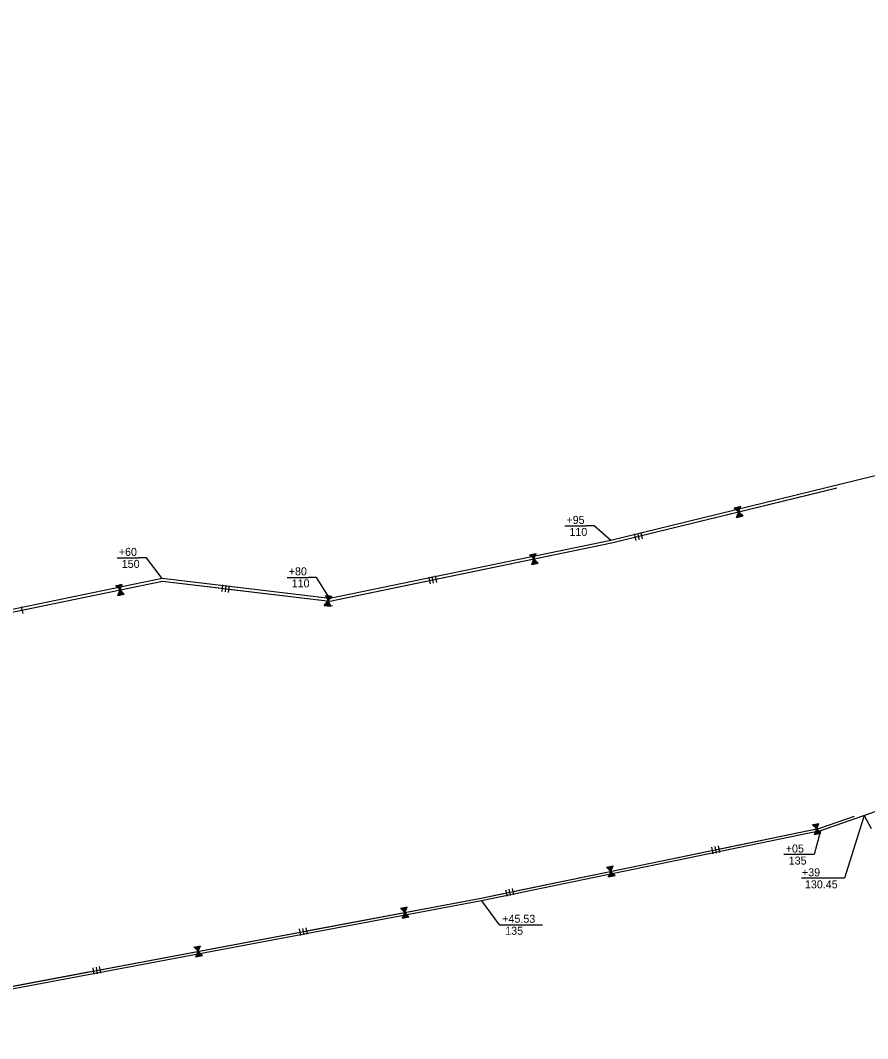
# Model space of a CAD drawing. Extents: x 979729 to 993523, y 1834148 to 1845433.
# Drawn here: x 989431 to 990066, y 1838597 to 1839360 of the extents above; entities that cross this region are included whole.
import ezdxf

# ---------------------------------------------------------------- set-up
doc = ezdxf.new("R2010")
doc.units = 0
for name, color, linetype in [('42', 7, 'Continuous'), ('51', 7, 'Continuous'), ('53', 7, 'Continuous'), ('R_Draft', 7, 'Continuous')]:
    doc.layers.add(name, color=color, linetype=linetype)

msp = doc.modelspace()

# ---------------------------------------------------------------- linework, layer by layer
at = {"layer": '42'}
for p, q in [((989873.61, 1838968.68), (990042.64, 1839010)), ((989967.98, 1838993.05), (989969, 1838995.86)), ((989968.16, 1838992.82), (989969.29, 1838995.93)), ((989968.36, 1838992.65), (989969.58, 1838996)), ((989968.56, 1838992.45), (989969.87, 1838996.07)), ((989968.77, 1838992.31), (989970.16, 1838996.15)), ((989968.96, 1838992.09), (989970.46, 1838996.22)), ((989969.02, 1838992), (989970.55, 1838996.24)), ((989965.7, 1838995.05), (989969.02, 1838992)), ((989965.76, 1838995.01), (989965.79, 1838995.08)), ((989965.97, 1838994.85), (989966.08, 1838995.15)), ((989966.16, 1838994.65), (989966.37, 1838995.22)), ((989966.37, 1838994.48), (989966.66, 1838995.29)), ((989966.56, 1838994.28), (989966.95, 1838995.36)), ((989966.76, 1838994.08), (989967.25, 1838995.43)), ((989966.96, 1838993.92), (989967.54, 1838995.5)), ((989967.19, 1838993.81), (989967.77, 1838995.42)), ((989967.37, 1838993.58), (989968.12, 1838995.65)), ((989967.48, 1838987.77), (989969.02, 1838992)), ((989967.58, 1838993.41), (989968.41, 1838995.72)), ((989967.7, 1838988.34), (989968.15, 1838987.93)), ((989967.76, 1838993.18), (989968.71, 1838995.79)), ((989967.81, 1838988.58), (989968.44, 1838988)), ((989967.89, 1838988.85), (989968.74, 1838988.08)), ((989967.97, 1838989.12), (989969.03, 1838988.15)), ((989968.07, 1838989.36), (989969.32, 1838988.22)), ((989968.23, 1838989.56), (989969.49, 1838988.4)), ((989968.28, 1838989.85), (989969.9, 1838988.36)), ((989968.39, 1838990.09), (989970.2, 1838988.43)), ((989968.44, 1838990.38), (989970.49, 1838988.5)), ((989968.57, 1838990.6), (989970.78, 1838988.57)), ((989968.63, 1838990.89), (989971.07, 1838988.65)), ((989968.74, 1838991.13), (989971.36, 1838988.72)), ((989968.81, 1838991.4), (989971.65, 1838988.79)), ((989968.94, 1838991.62), (989971.95, 1838988.86)), ((989969, 1838991.91), (989972.24, 1838988.93)), ((989969.02, 1838992), (989972.33, 1838988.95)), ((989967.52, 1838987.83), (989967.57, 1838987.79)), ((989967.63, 1838988.08), (989967.86, 1838987.86)), ((989890.71, 1838975.44), (989891.9, 1838970.58)), ((989893.14, 1838976.03), (989894.33, 1838971.17)), ((989895.57, 1838976.62), (989896.75, 1838971.77)), ((989662.7, 1838925.14), (989873.61, 1838968.68)), ((989812.34, 1838959.86), (989815.55, 1838956.7)), ((989812.41, 1838959.82), (989812.43, 1838959.88)), ((989812.61, 1838959.65), (989812.73, 1838959.94)), ((989812.79, 1838959.44), (989813.02, 1838960.01)), ((989813, 1838959.27), (989813.32, 1838960.07)), ((989813.18, 1838959.06), (989813.61, 1838960.13)), ((989813.37, 1838958.85), (989813.9, 1838960.19)), ((989813.57, 1838958.68), (989814.2, 1838960.25)), ((989813.79, 1838958.57), (989814.43, 1838960.15)), ((989813.96, 1838958.33), (989814.79, 1838960.37)), ((989814.16, 1838958.16), (989815.08, 1838960.43)), ((989814.34, 1838957.92), (989815.38, 1838960.49)), ((989814.55, 1838957.78), (989815.67, 1838960.55)), ((989814.72, 1838957.54), (989815.96, 1838960.61)), ((989814.92, 1838957.37), (989816.26, 1838960.67)), ((989815.11, 1838957.16), (989816.55, 1838960.73)), ((989815.32, 1838957.02), (989816.85, 1838960.79)), ((989815.49, 1838956.78), (989817.14, 1838960.86)), ((989815.55, 1838956.7), (989817.24, 1838960.88)), ((989813.86, 1838952.52), (989815.55, 1838956.7)), ((989813.9, 1838952.59), (989813.95, 1838952.54)), ((989814.02, 1838952.82), (989814.24, 1838952.6)), ((989814.11, 1838953.09), (989814.54, 1838952.66)), ((989814.22, 1838953.32), (989814.83, 1838952.72)), ((989814.31, 1838953.59), (989815.13, 1838952.78)), ((989814.4, 1838953.85), (989815.42, 1838952.84)), ((989814.51, 1838954.09), (989815.71, 1838952.9)), ((989814.67, 1838954.28), (989815.89, 1838953.08)), ((989814.74, 1838954.57), (989816.3, 1838953.02)), ((989814.85, 1838954.81), (989816.6, 1838953.09)), ((989814.92, 1838955.09), (989816.89, 1838953.15)), ((989815.06, 1838955.31), (989817.19, 1838953.21)), ((989815.12, 1838955.6), (989817.48, 1838953.27)), ((989815.24, 1838955.83), (989817.77, 1838953.33)), ((989815.33, 1838956.1), (989818.07, 1838953.39)), ((989815.46, 1838956.31), (989818.36, 1838953.45)), ((989815.53, 1838956.6), (989818.66, 1838953.51)), ((989815.55, 1838956.7), (989818.75, 1838953.53)), ((989736.69, 1838942.97), (989737.71, 1838938.07)), ((989739.14, 1838943.48), (989740.15, 1838938.58)), ((989741.59, 1838943.98), (989742.6, 1838939.09)), ((989341.75, 1838899.73), (989537.09, 1838940.06)), ((989502.12, 1838936.66), (989505.32, 1838933.5)), ((989502.18, 1838936.62), (989502.21, 1838936.68)), ((989502.38, 1838936.45), (989502.5, 1838936.74)), ((989502.57, 1838936.24), (989502.8, 1838936.81)), ((989502.77, 1838936.07), (989503.09, 1838936.87)), ((989502.95, 1838935.86), (989503.39, 1838936.93)), ((989503.14, 1838935.65), (989503.68, 1838936.99)), ((989503.34, 1838935.48), (989503.97, 1838937.05)), ((989503.56, 1838935.37), (989504.21, 1838936.96)), ((989503.74, 1838935.13), (989504.56, 1838937.17)), ((989503.94, 1838934.96), (989504.86, 1838937.23)), ((989504.11, 1838934.72), (989505.15, 1838937.29)), ((989504.32, 1838934.58), (989505.45, 1838937.35)), ((989504.5, 1838934.34), (989505.74, 1838937.41)), ((989504.7, 1838934.17), (989506.03, 1838937.47)), ((989504.88, 1838933.96), (989506.33, 1838937.53)), ((989505.09, 1838933.82), (989506.62, 1838937.59)), ((989505.27, 1838933.58), (989506.92, 1838937.66)), ((989505.32, 1838933.5), (989507.01, 1838937.68)), ((989537.09, 1838940.06), (989662.7, 1838925.14)), ((989582.13, 1838937.23), (989581.54, 1838932.26)), ((989584.62, 1838936.93), (989584.03, 1838931.97)), ((989587.1, 1838936.64), (989586.51, 1838931.67)), ((989503.63, 1838929.32), (989505.32, 1838933.5)), ((989503.68, 1838929.39), (989503.72, 1838929.34)), ((989503.79, 1838929.62), (989504.02, 1838929.4)), ((989503.88, 1838929.89), (989504.31, 1838929.46)), ((989504, 1838930.12), (989504.61, 1838929.52)), ((989504.08, 1838930.39), (989504.9, 1838929.58)), ((989504.17, 1838930.65), (989505.2, 1838929.64)), ((989504.29, 1838930.89), (989505.49, 1838929.7)), ((989504.45, 1838931.08), (989505.67, 1838929.88)), ((989504.51, 1838931.37), (989506.08, 1838929.82)), ((989504.63, 1838931.61), (989506.37, 1838929.89)), ((989504.69, 1838931.89), (989506.67, 1838929.95)), ((989504.83, 1838932.11), (989506.96, 1838930.01)), ((989504.9, 1838932.4), (989507.26, 1838930.07)), ((989505.01, 1838932.63), (989507.55, 1838930.13)), ((989505.1, 1838932.9), (989507.84, 1838930.19)), ((989505.24, 1838933.11), (989508.14, 1838930.25)), ((989505.3, 1838933.4), (989508.43, 1838930.31)), ((989505.32, 1838933.5), (989508.53, 1838930.33)), ((989659.24, 1838929.33), (989661.28, 1838925.31)), ((989659.29, 1838929.27), (989659.33, 1838929.32)), ((989659.43, 1838929.04), (989659.63, 1838929.28)), ((989659.54, 1838928.79), (989659.93, 1838929.25)), ((989659.67, 1838928.56), (989660.23, 1838929.21)), ((989659.78, 1838928.3), (989660.53, 1838929.18)), ((989659.89, 1838928.05), (989660.83, 1838929.14)), ((989660.03, 1838927.82), (989661.12, 1838929.11)), ((989660.2, 1838927.65), (989661.31, 1838928.95)), ((989660.29, 1838927.36), (989661.72, 1838929.04)), ((989660.43, 1838927.13), (989662.02, 1838929)), ((989660.52, 1838926.86), (989662.32, 1838928.97)), ((989660.67, 1838926.65), (989662.62, 1838928.93)), ((989660.76, 1838926.37), (989662.91, 1838928.89)), ((989660.9, 1838926.15), (989663.21, 1838928.86)), ((989661.01, 1838925.89), (989663.51, 1838928.82)), ((989661.16, 1838925.69), (989663.81, 1838928.79)), ((989661.25, 1838925.41), (989664.11, 1838928.75)), ((989661.28, 1838925.31), (989664.21, 1838928.74)), ((989431.37, 1838920.78), (989432.38, 1838915.89)), ((989658.36, 1838921.88), (989661.28, 1838925.31)), ((989658.42, 1838921.93), (989658.45, 1838921.87)), ((989658.61, 1838922.12), (989658.75, 1838921.84)), ((989658.77, 1838922.34), (989659.05, 1838921.8)), ((989658.96, 1838922.53), (989659.34, 1838921.77)), ((989659.12, 1838922.75), (989659.64, 1838921.73)), ((989659.29, 1838922.98), (989659.94, 1838921.69)), ((989659.47, 1838923.17), (989660.24, 1838921.66)), ((989659.69, 1838923.3), (989660.46, 1838921.77)), ((989659.84, 1838923.55), (989660.84, 1838921.59)), ((989660.02, 1838923.74), (989661.14, 1838921.55)), ((989660.18, 1838923.99), (989661.43, 1838921.52)), ((989660.38, 1838924.15), (989661.73, 1838921.48)), ((989660.53, 1838924.4), (989662.03, 1838921.45)), ((989660.71, 1838924.59), (989662.33, 1838921.41)), ((989660.88, 1838924.81), (989662.63, 1838921.38)), ((989661.08, 1838924.98), (989662.92, 1838921.34)), ((989661.23, 1838925.23), (989663.22, 1838921.31)), ((989661.28, 1838925.31), (989663.32, 1838921.29)), ((990029.9, 1838754.87), (990055.74, 1838763.89)), ((989775.94, 1838702.44), (990029.9, 1838754.87)), ((990024.25, 1838757.53), (990027.46, 1838754.36)), ((990024.32, 1838757.49), (990024.34, 1838757.55)), ((990024.52, 1838757.32), (990024.64, 1838757.61)), ((990024.7, 1838757.11), (990024.93, 1838757.67)), ((990024.9, 1838756.94), (990025.23, 1838757.73)), ((990025.09, 1838756.73), (990025.52, 1838757.79)), ((990025.27, 1838756.52), (990025.81, 1838757.85)), ((990025.47, 1838756.35), (990026.11, 1838757.91)), ((990025.7, 1838756.24), (990026.34, 1838757.82)), ((990025.77, 1838750.18), (990027.46, 1838754.36)), ((990025.87, 1838755.99), (990026.7, 1838758.03)), ((990026.07, 1838755.82), (990026.99, 1838758.1)), ((990026.25, 1838755.59), (990027.29, 1838758.16)), ((990026.42, 1838751.76), (990027.62, 1838750.57)), ((990026.46, 1838755.44), (990027.58, 1838758.22)), ((990026.58, 1838751.95), (990027.8, 1838750.75)), ((990026.63, 1838755.21), (990027.87, 1838758.28)), ((990026.65, 1838752.24), (990028.21, 1838750.69)), ((990026.76, 1838752.47), (990028.51, 1838750.75)), ((990026.83, 1838755.04), (990028.17, 1838758.34)), ((990026.83, 1838752.76), (990028.8, 1838750.81)), ((990026.97, 1838752.98), (990029.1, 1838750.87)), ((990027.02, 1838754.83), (990028.46, 1838758.4)), ((990027.03, 1838753.26), (990029.39, 1838750.93)), ((990027.15, 1838753.5), (990029.68, 1838750.99)), ((990027.23, 1838754.68), (990028.76, 1838758.46)), ((990027.24, 1838753.76), (990029.98, 1838751.05)), ((990027.37, 1838753.98), (990030.27, 1838751.11)), ((990027.4, 1838754.45), (990029.05, 1838758.52)), ((990027.44, 1838754.26), (990030.57, 1838751.18)), ((990027.46, 1838754.36), (990029.15, 1838758.54)), ((990027.46, 1838754.36), (990030.66, 1838751.2)), ((990025.81, 1838750.25), (990025.86, 1838750.2)), ((990025.93, 1838750.49), (990026.15, 1838750.26)), ((990026.02, 1838750.75), (990026.45, 1838750.32)), ((990026.13, 1838750.99), (990026.74, 1838750.39)), ((990026.22, 1838751.25), (990027.04, 1838750.45)), ((990026.31, 1838751.52), (990027.33, 1838750.51)), ((989948.6, 1838740.64), (989949.62, 1838735.74)), ((989951.05, 1838741.14), (989952.06, 1838736.25)), ((989953.5, 1838741.65), (989954.51, 1838736.75)), ((989870, 1838725.69), (989873.21, 1838722.52)), ((989870.07, 1838725.65), (989870.09, 1838725.71)), ((989870.27, 1838725.47), (989870.39, 1838725.77)), ((989870.46, 1838725.26), (989870.68, 1838725.83)), ((989870.66, 1838725.09), (989870.98, 1838725.89)), ((989870.84, 1838724.88), (989871.27, 1838725.95)), ((989871.03, 1838724.68), (989871.57, 1838726.01)), ((989871.23, 1838724.5), (989871.86, 1838726.07)), ((989871.45, 1838724.39), (989872.09, 1838725.98)), ((989871.52, 1838718.34), (989873.21, 1838722.52)), ((989871.62, 1838724.15), (989872.45, 1838726.19)), ((989871.82, 1838723.98), (989872.74, 1838726.25)), ((989872, 1838723.74), (989873.04, 1838726.31)), ((989872.21, 1838723.6), (989873.33, 1838726.37)), ((989872.38, 1838723.36), (989873.63, 1838726.43)), ((989872.58, 1838723.19), (989873.92, 1838726.5)), ((989872.72, 1838721.13), (989874.85, 1838719.03)), ((989872.77, 1838722.98), (989874.21, 1838726.56)), ((989872.79, 1838721.42), (989875.14, 1838719.09)), ((989872.9, 1838721.65), (989875.44, 1838719.15)), ((989872.98, 1838722.84), (989874.51, 1838726.62)), ((989872.99, 1838721.92), (989875.73, 1838719.21)), ((989873.12, 1838722.14), (989876.03, 1838719.27)), ((989873.15, 1838722.6), (989874.8, 1838726.68)), ((989873.19, 1838722.42), (989876.32, 1838719.33)), ((989873.21, 1838722.52), (989874.9, 1838726.7)), ((989873.21, 1838722.52), (989876.42, 1838719.35)), ((989871.56, 1838718.41), (989871.61, 1838718.36)), ((989871.68, 1838718.64), (989871.91, 1838718.42)), ((989871.77, 1838718.91), (989872.2, 1838718.48)), ((989871.89, 1838719.14), (989872.49, 1838718.54)), ((989871.97, 1838719.41), (989872.79, 1838718.6)), ((989872.06, 1838719.67), (989873.08, 1838718.66)), ((989872.17, 1838719.91), (989873.38, 1838718.72)), ((989872.34, 1838720.1), (989873.55, 1838718.9)), ((989872.4, 1838720.39), (989873.97, 1838718.85)), ((989872.51, 1838720.63), (989874.26, 1838718.91)), ((989872.58, 1838720.92), (989874.55, 1838718.97)), ((989794.36, 1838708.79), (989795.37, 1838703.9)), ((989796.81, 1838709.3), (989797.82, 1838704.4)), ((989799.25, 1838709.8), (989800.26, 1838704.91)), ((989226.06, 1838599.13), (989775.94, 1838702.44)), ((989715.61, 1838694.92), (989718.76, 1838691.7)), ((989715.68, 1838694.88), (989715.7, 1838694.94)), ((989715.88, 1838694.7), (989716, 1838694.99)), ((989716.06, 1838694.49), (989716.29, 1838695.05)), ((989716.25, 1838694.32), (989716.59, 1838695.1)), ((989716.44, 1838694.1), (989716.89, 1838695.16)), ((989716.62, 1838693.89), (989717.18, 1838695.22)), ((989716.81, 1838693.72), (989717.48, 1838695.27)), ((989717, 1838687.55), (989718.76, 1838691.7)), ((989717.04, 1838693.6), (989717.71, 1838695.17)), ((989717.2, 1838693.35), (989718.07, 1838695.38)), ((989717.4, 1838693.18), (989718.36, 1838695.44)), ((989717.57, 1838692.94), (989718.66, 1838695.49)), ((989717.78, 1838692.79), (989718.95, 1838695.55)), ((989717.95, 1838692.55), (989719.25, 1838695.6)), ((989718.15, 1838692.38), (989719.54, 1838695.66)), ((989718.32, 1838690.6), (989720.63, 1838688.23)), ((989718.33, 1838692.17), (989719.84, 1838695.71)), ((989718.44, 1838690.84), (989720.93, 1838688.29)), ((989718.53, 1838691.1), (989721.22, 1838688.34)), ((989718.54, 1838692.02), (989720.13, 1838695.77)), ((989718.67, 1838691.31), (989721.52, 1838688.4)), ((989718.71, 1838691.78), (989720.43, 1838695.83)), ((989718.74, 1838691.6), (989721.81, 1838688.45)), ((989718.76, 1838691.7), (989720.53, 1838695.84)), ((989718.76, 1838691.7), (989721.91, 1838688.47)), ((989717.04, 1838687.61), (989717.09, 1838687.57)), ((989717.16, 1838687.85), (989717.38, 1838687.62)), ((989717.25, 1838688.11), (989717.68, 1838687.68)), ((989717.38, 1838688.35), (989717.97, 1838687.73)), ((989717.47, 1838688.61), (989718.27, 1838687.79)), ((989717.56, 1838688.87), (989718.57, 1838687.84)), ((989717.68, 1838689.11), (989718.86, 1838687.9)), ((989717.85, 1838689.3), (989719.04, 1838688.07)), ((989717.91, 1838689.59), (989719.45, 1838688.01)), ((989718.03, 1838689.82), (989719.75, 1838688.07)), ((989718.1, 1838690.1), (989720.04, 1838688.12)), ((989718.25, 1838690.32), (989720.34, 1838688.18)), ((989639.68, 1838679.38), (989640.6, 1838674.47)), ((989642.13, 1838679.84), (989643.06, 1838674.93)), ((989644.59, 1838680.31), (989645.51, 1838675.39)), ((989560.82, 1838665.84), (989563.97, 1838662.62)), ((989560.89, 1838665.8), (989560.91, 1838665.86)), ((989561.08, 1838665.62), (989561.21, 1838665.91)), ((989561.26, 1838665.41), (989561.5, 1838665.97)), ((989561.46, 1838665.23), (989561.8, 1838666.02)), ((989561.64, 1838665.02), (989562.09, 1838666.08)), ((989561.83, 1838664.81), (989562.39, 1838666.13)), ((989562.02, 1838664.64), (989562.68, 1838666.19)), ((989562.21, 1838658.47), (989563.97, 1838662.62)), ((989562.24, 1838664.52), (989562.91, 1838666.09)), ((989562.41, 1838664.27), (989563.27, 1838666.3)), ((989562.61, 1838664.1), (989563.57, 1838666.36)), ((989562.78, 1838663.86), (989563.87, 1838666.41)), ((989562.89, 1838660.03), (989564.07, 1838658.82)), ((989562.99, 1838663.71), (989564.16, 1838666.47)), ((989563.05, 1838660.21), (989564.25, 1838658.99)), ((989563.12, 1838660.51), (989564.66, 1838658.93)), ((989563.16, 1838663.47), (989564.46, 1838666.52)), ((989563.24, 1838660.74), (989564.96, 1838658.98)), ((989563.31, 1838661.02), (989565.25, 1838659.04)), ((989563.35, 1838663.3), (989564.75, 1838666.58)), ((989563.45, 1838661.24), (989565.55, 1838659.1)), ((989563.53, 1838661.52), (989565.84, 1838659.15)), ((989563.54, 1838663.09), (989565.05, 1838666.63)), ((989563.64, 1838661.76), (989566.14, 1838659.21)), ((989563.74, 1838662.94), (989565.34, 1838666.69)), ((989563.74, 1838662.02), (989566.43, 1838659.26)), ((989563.88, 1838662.23), (989566.73, 1838659.32)), ((989563.92, 1838662.7), (989565.64, 1838666.74)), ((989563.95, 1838662.52), (989567.02, 1838659.37)), ((989563.97, 1838662.62), (989565.73, 1838666.76)), ((989563.97, 1838662.62), (989567.12, 1838659.39)), ((989562.25, 1838658.53), (989562.3, 1838658.49)), ((989562.37, 1838658.77), (989562.59, 1838658.54)), ((989562.46, 1838659.03), (989562.89, 1838658.6)), ((989562.58, 1838659.27), (989563.18, 1838658.65)), ((989562.68, 1838659.53), (989563.48, 1838658.71)), ((989562.77, 1838659.79), (989563.77, 1838658.76)), ((989484.88, 1838650.3), (989485.81, 1838645.39)), ((989487.34, 1838650.76), (989488.26, 1838645.85)), ((989489.8, 1838651.22), (989490.72, 1838646.31))]:
    msp.add_line(p, q, dxfattribs=at)
for points in [[(989896.16, 1838974.2), (990041.87, 1839009.81)], [(989965.7, 1838995.05), (989970.55, 1838996.24)], [(989967.48, 1838987.77), (989972.33, 1838988.95)], [(989742.1, 1838941.53), (989873.61, 1838968.68), (989888.87, 1838972.41)], [(989812.34, 1838959.86), (989817.24, 1838960.88)], [(989813.86, 1838952.52), (989818.75, 1838953.53)], [(989431.87, 1838918.33), (989537.09, 1838940.06), (989579.36, 1838935.04)], [(989502.12, 1838936.66), (989507.01, 1838937.68)], [(989586.8, 1838934.15), (989662.7, 1838925.14), (989734.75, 1838940.02)], [(989503.63, 1838929.32), (989508.53, 1838930.33)], [(989659.24, 1838929.33), (989662.54, 1838928.94), (989662.99, 1838929.03)], [(989658.36, 1838921.88), (989662.86, 1838921.35), (989664.51, 1838921.69)], [(989954.01, 1838739.2), (990029.9, 1838754.87), (990055.74, 1838763.89)], [(990024.25, 1838757.53), (990029.14, 1838758.54)], [(990025.77, 1838750.18), (990030.66, 1838751.19)], [(989799.76, 1838707.36), (989946.66, 1838737.68)], [(989870, 1838725.69), (989874.9, 1838726.7)], [(989871.52, 1838718.34), (989876.42, 1838719.35)], [(989645.05, 1838677.85), (989775.94, 1838702.44), (989792.41, 1838705.84)], [(989715.61, 1838694.92), (989720.53, 1838695.84)], [(989717, 1838687.55), (989721.91, 1838688.47)], [(989490.26, 1838648.77), (989637.68, 1838676.46)], [(989560.82, 1838665.84), (989565.73, 1838666.76)], [(989562.21, 1838658.47), (989567.12, 1838659.39)], [(989335.47, 1838619.69), (989482.89, 1838647.38)]]:
    msp.add_lwpolyline(points, dxfattribs=at)
at = {"layer": '51'}
msp.add_line((989776.33, 1838700.48), (989226.43, 1838597.17), dxfattribs=at)
for points in [[(990790.39, 1839360.39), (990495.54, 1839185.59), (990219.53, 1839055.3), (989873.17, 1838970.64), (989662.61, 1838927.17), (989537.01, 1838942.08), (989341.14, 1838901.64), (989234.92, 1838854.19)], [(990778.93, 1839076.47), (990597.42, 1838950.97), (990030.44, 1838752.94), (989776.33, 1838700.48)]]:
    msp.add_lwpolyline(points, dxfattribs=at)
at = {"layer": '53'}
msp.add_line((990062.99, 1838764.31), (990068.29, 1838754.63), dxfattribs=at)
at = {"layer": 'R_Draft'}
for p, q in [((989838.82, 1838981.46), (989854.62, 1838981.46)), ((989503.31, 1838957.51), (989519.11, 1838957.51)), ((989630.7, 1838942.91), (989646.5, 1838942.91)), ((990019.67, 1838735.13), (990002.9, 1838735.13)), ((990042.41, 1838717.32), (990016.01, 1838717.32)), ((989795.4, 1838682.52), (989821.99, 1838682.52))]:
    msp.add_line(p, q, dxfattribs=at)
for points in [[(989873.17, 1838970.64), (989860.62, 1838981.46), (989854.62, 1838981.46)], [(989537.01, 1838942.08), (989525.11, 1838957.51), (989519.11, 1838957.51)], [(989662.61, 1838927.17), (989652.5, 1838942.91), (989646.5, 1838942.91)], [(990062.99, 1838764.31), (990048.41, 1838717.32), (990042.41, 1838717.32)], [(990030.44, 1838752.94), (990025.67, 1838735.13), (990019.67, 1838735.13)], [(989776.33, 1838700.48), (989789.4, 1838682.52), (989795.4, 1838682.52)]]:
    msp.add_lwpolyline(points, dxfattribs=at)

# ---------------------------------------------------------------- texts
for s, p in [('+95', (989839.91, 1838982.96)), (' 110', (989839.91, 1838973.96)), ('+60', (989504.4, 1838959.01)), (' 150', (989504.4, 1838950.01)), ('+80', (989631.79, 1838944.41)), (' 110', (989631.79, 1838935.41)), ('+05', (990004.26, 1838736.63)), (' 135', (990004.26, 1838727.63)), ('+39', (990016.42, 1838718.82)), (' 130.45', (990016.42, 1838709.82)), ('+45.53', (989791.78, 1838684.02)), (' 135', (989791.78, 1838675.02))]:
    msp.add_text(s, height=6, rotation=360, dxfattribs=at).set_placement(p)

doc.saveas('drawing.dxf')
